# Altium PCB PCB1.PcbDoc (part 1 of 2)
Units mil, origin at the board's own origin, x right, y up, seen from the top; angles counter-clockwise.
Board outline 1968.5 x 1968.5 mil, 2 copper layers (Top Layer, Bottom Layer); 81 components, 57 nets, 327 pads, 270 vias.
Unrouted connection lines stored in the file: 104.
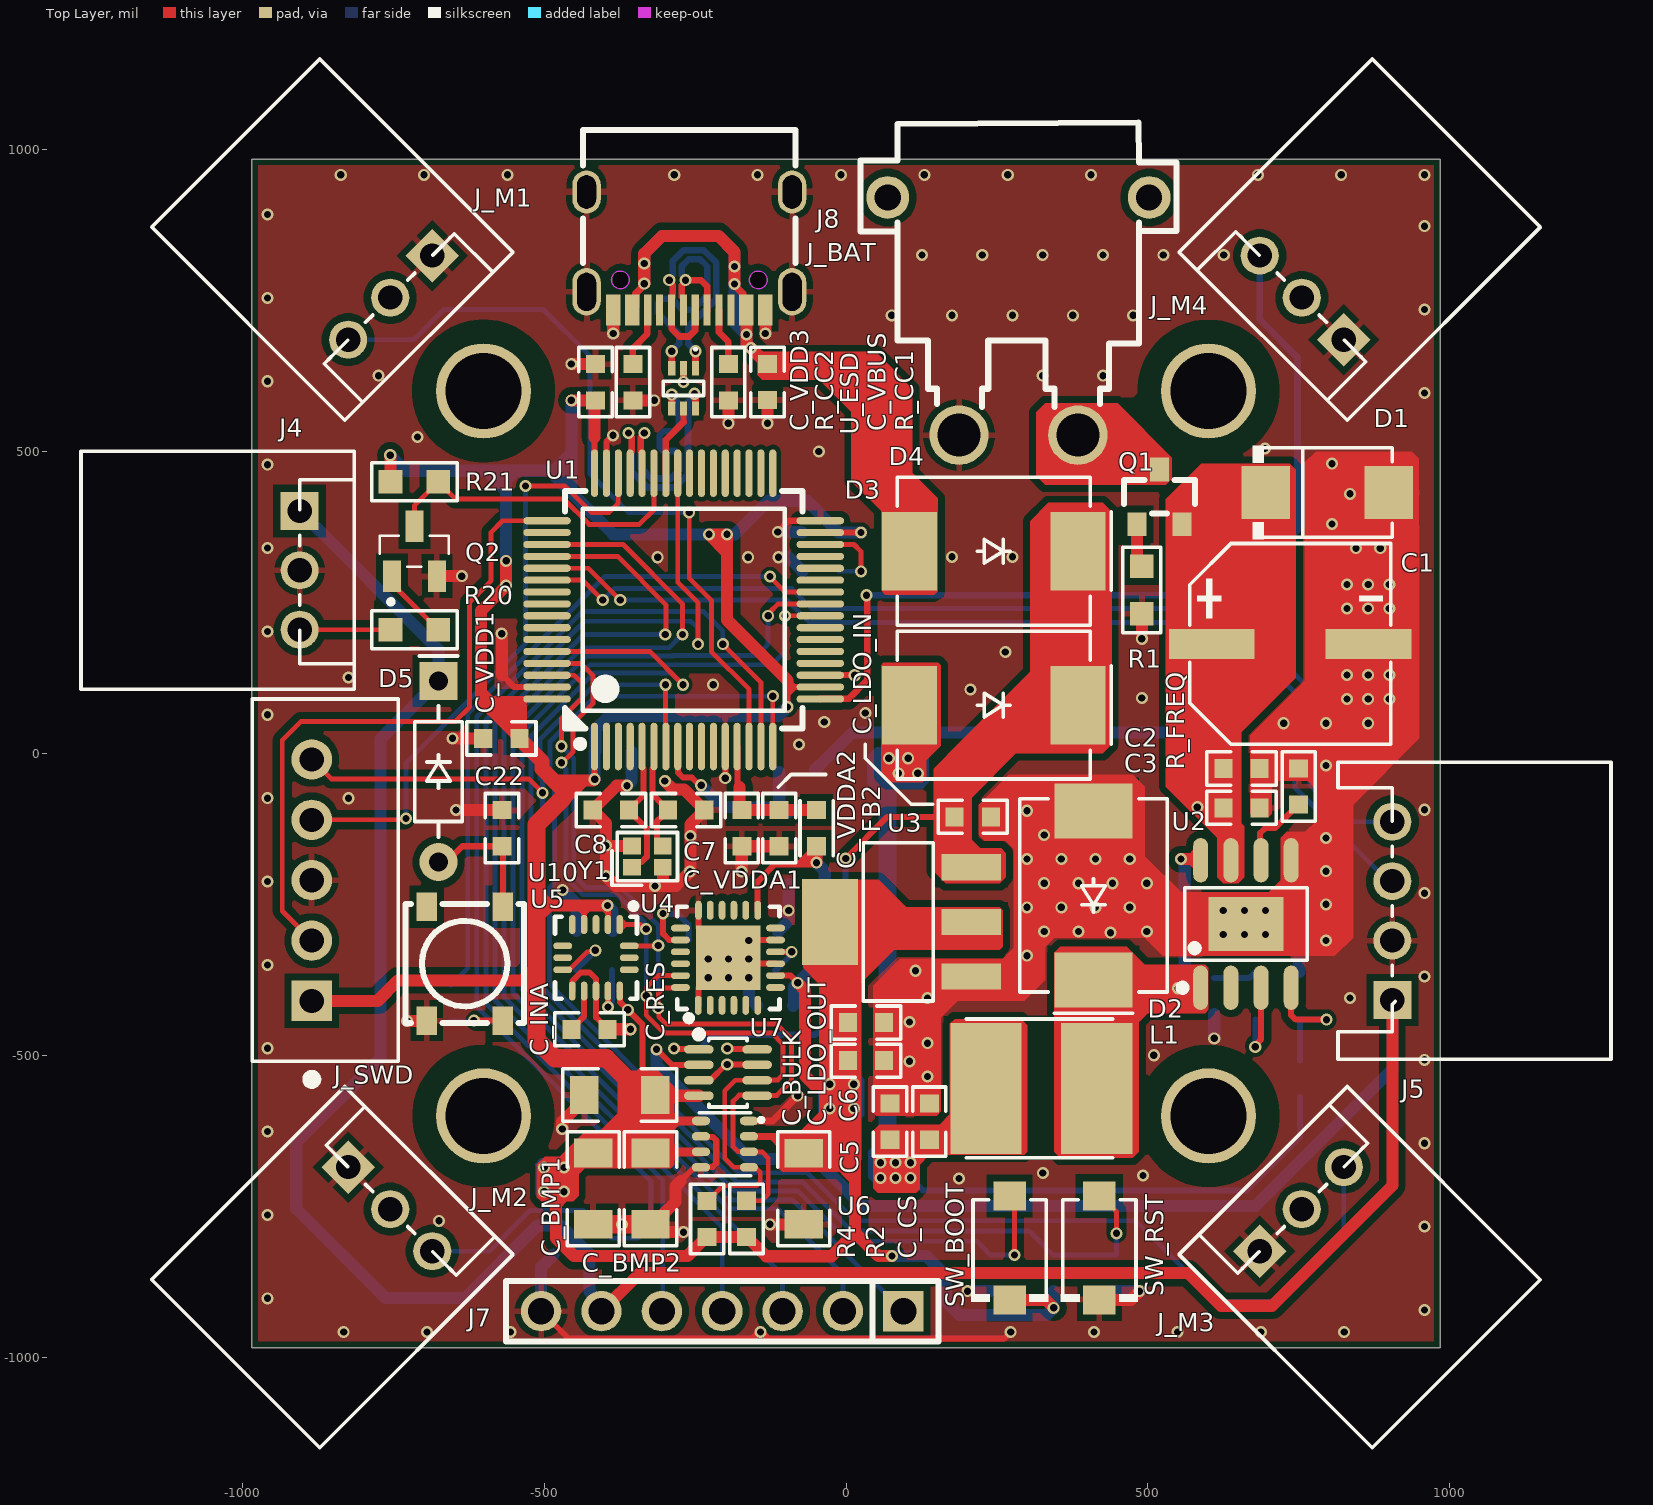
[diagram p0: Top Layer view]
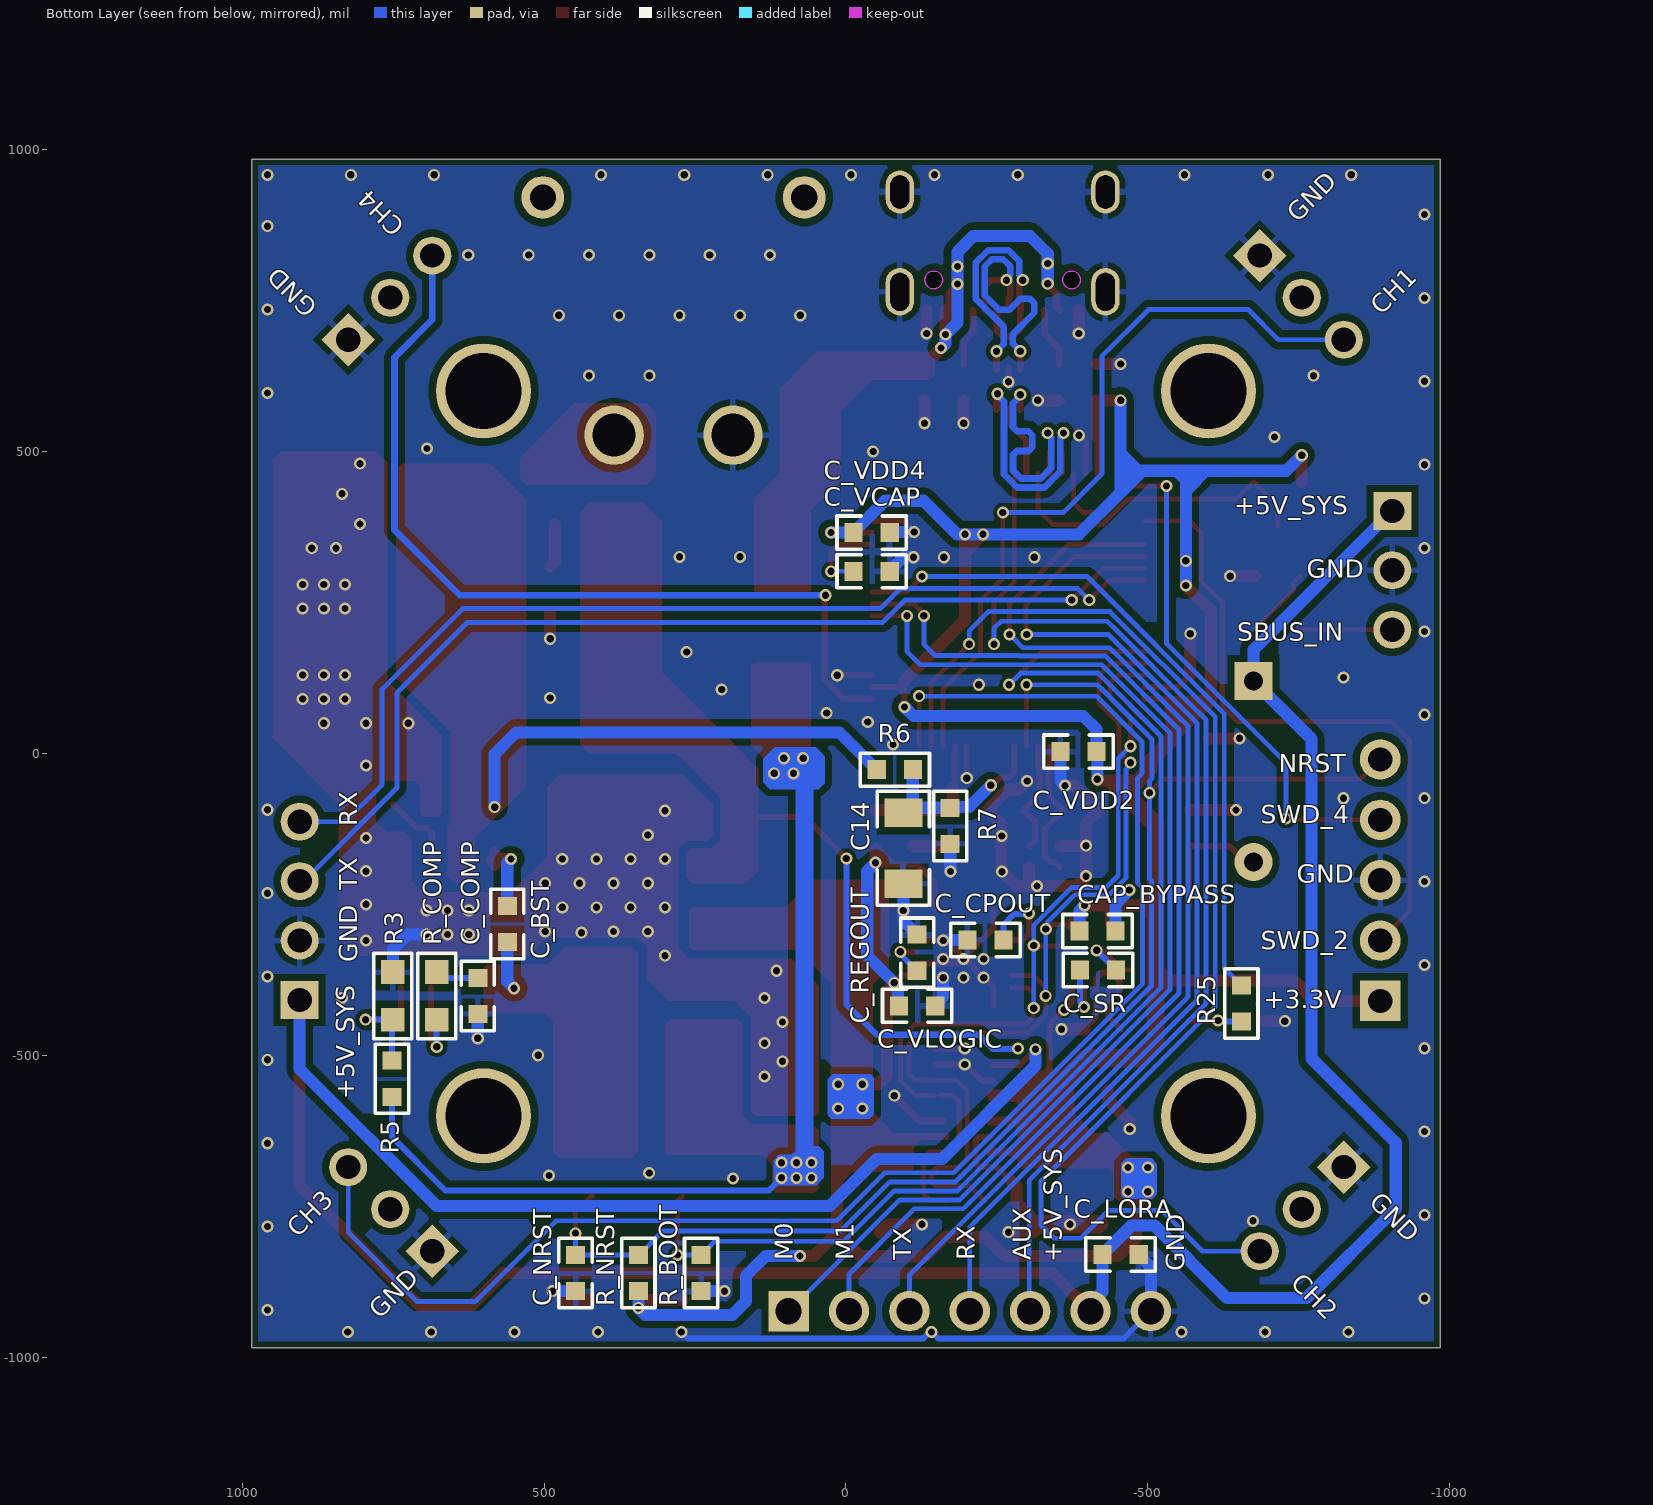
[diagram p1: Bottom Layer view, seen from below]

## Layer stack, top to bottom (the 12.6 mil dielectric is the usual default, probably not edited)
Top Solder: solder mask 0.4, Solder Resist, Dk 3.5
Top Layer: signal copper 1.4
Dielectric 1: dielectric 12.6, FR-4, Dk 4.8
Bottom Layer: signal copper 1.4
Bottom Solder: solder mask 0.4, Solder Resist, Dk 3.5

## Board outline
-984.25,-984.25 -984.25,984.25 984.25,984.25 984.25,-984.25

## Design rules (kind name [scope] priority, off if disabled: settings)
BoardOutlineClearance [All] p1: gap=10 ignorepadtopadclearanceinfootprint=FALSE except(0: Arc-SplitContinuation Track-SplitContinuation SMDPad-SplitContinuation THPad-SplitContinuation Via-SplitContinuation Fill-SplitContinuation Poly-SplitContinuation Region-SplitContinuation Text-SplitContinuation)
Clearance USB [WithinRoom('RoomDefinition')] p1: gap=5 ignorepadtopadclearanceinfootprint=FALSE except(4: Arc-Arc Arc-Track Track-Track; 8: SMDPad-Fill SMDPad-Poly SMDPad-Region; 12: Arc-Fill Arc-Poly Arc-Region Track-Fill Track-Poly Track-Region THPad-Fill THPad-Poly THPad-Region Fill-Fill Fill-Poly Fill-Region Poly-Poly Poly-Region Region-Region)
Clearance [All] p2: gap=4 ignorepadtopadclearanceinfootprint=FALSE except(12: Arc-Fill Arc-Poly Arc-Region Track-Fill Track-Poly Track-Region SMDPad-Fill SMDPad-Poly SMDPad-Region THPad-Fill THPad-Poly THPad-Region Fill-Fill Fill-Poly Fill-Region Poly-Poly Poly-Region Region-Region)
DiffPairsRouting [InDifferentialPairClass('All Differential Pairs')] p1: maxlimit=4 minlimit=4 mostfreqgap=4 toplayer_minwidth=10.9 toplayer_maxwidth=10.9 toplayer_prefwidth=10.9 bottomlayer_minwidth=10.9 bottomlayer_maxwidth=10.9 bottomlayer_prefwidth=10.9 maxuncoupledlength=500
MatchedLengths [InDifferentialPairClass('All Differential Pairs')] p1: tolerance=5 checknetsindiffpair=TRUE checkdiffpairvsdiffpair=FALSE checkxsignals=FALSE checkothers=FALSE
PlaneClearance [All] p1: clearance=8
PlaneConnect [All] p1: planeconnectstyle=Direct reliefexpansion=20 reliefentries=4 reliefconductorwidth=10 reliefairgap=10
PolygonConnect [All] p1: thpad.connectstyle=Relief thpad.reliefconductorwidth=10 thpad.reliefentries=4 thpad.polygonreliefangle="90 Angle" thpad.airgapwidth=10 smdpad.connectstyle=Relief smdpad.reliefconductorwidth=10 smdpad.reliefentries=4 smdpad.polygonreliefangle="90 Angle" smdpad.airgapwidth=10 via.connectstyle=Direct via.reliefconductorwidth=10 via.reliefentries=4 via.polygonreliefangle="90 Angle" via.airgapwidth=10
RoomDefinition [False vs False] p1: confinementstyle=ConfineIn formatcopy=TRUE lockcomponents=FALSE outline -460,1049 -96.52,1049 -96.52,418.56 -460,418.56
RoutingVias [All] p1: holewidth=12 width=20 viastyle="Through Hole" minholewidth=12 minwidth=20 maxholewidth=12 maxwidth=20
SolderMaskExpansion [All] p1: expansion=4 istentingtop=FALSE
UnRoutedNet [All] p1: checkbadconnections=TRUE
Width PWR [InNetClass('PWR')] p1: maxlimit=100 minlimit=10 preferedwidth=20
Width [All] p2: maxlimit=100 minlimit=6 preferedwidth=8
26 further rules are at their usual default settings.

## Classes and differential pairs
component class "Room Definition1": R_CC1
net class PWR: +3.3V +5V_SYS GND NetC1_1 NetC5_1 VBUS
component class "USB-C (Power + DFU), Diode-OR, 3.3V LDO": C_BULK C_LDO_IN C_LDO_OUT C_VBUS C_VDD1 C_VDD2 C_VDD3 C_VDD4 D3 D4 J8 R_CC1 R_CC2 SW_BOOT SW_RST U3 U_ESD
component class "STM32F446RET6 Core": U1
component class "RC INPUT, STATUS LED, SWD HEADER": C22 D5 J_SWD Q2 R20 R21 R25 U10
component class "MCU Support Circuit": C7 C8 C_NRST C_VCAP C_VDDA1 C_VDDA2 FB2 R_BOOT R_NRST Y1
component class "I2C SENSORS B - BAROMETER, CURRENT MONITOR, BATTERY SENSE": C14 C_BMP1 C_BMP2 C_CS C_INA R6 R7 U6 U7
component class "I2C Sensors A- IMU and Magnetometer": C_CPOUT C_REGOUT C_RES C_SR C_VLOGIC CAP_BYPASS R2 R4 U4 U5
component class "EXTERNAL CONNECTORS": C_LORA J4 J5 J7 J_BAT J_M1 J_M2 J_M3 J_M4
component class "Battery Input, Protection, 5.2V Buck": C1 C2 C3 C5 C6 C_BST C_COMP D1 D2 L1 Q1 R1 R3 R5 R_COMP R_FREQ U2
differential pair USB1: +NetJ8_A6 -NetJ8_A7
differential pair USB: +USB_DM -NetU1_45

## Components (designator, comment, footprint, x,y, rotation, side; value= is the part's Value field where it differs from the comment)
C1 "220uF" CAP-SMD_BD8.0-L8.3-W8.3-LS9.1-FD 735,180 r0 top
C2 "100nF" 0603C 654.92,-25 r0 top
C3 "10uF" 0603C 654.92,-90 r0 top
C5 "22uF" 0603C 138,-610.08 r90 top
C6 "100nF" 0603C 73,-610.08 r90 top
C7 "100nF" 0603C -264.72,-93.91 r0 top
C8 "100nF" 0603C -389.56,-93.91 r180 top
C14 "100nF" 1206C -95,-156.97 r270 bottom
C22 "100nF" 0603C -570,-123.83 r90 top
C_BMP1 "100nF" 1206C -418.69,-720.96 r270 top
C_BMP2 "100nF" 1206C -323.69,-720.96 r270 top
C_BST "100nF" 0603C 561.13,-282.56 r270 bottom
C_BULK "2.2uF" 0603C 33.35,-445.98 r0 top
C_COMP "150pF" 0603C 610,-401.63 r270 bottom
C_CPOUT "100nF" 0603C -230.92,-309 r180 bottom
C_CS "100nF" 1206C -70,-721 r270 top
C_INA "100nF" 1206C -374.87,-566 r180 top
C_LDO_IN "10uF" 0603C 210,-105 r0 top
C_LDO_OUT "22uF" 0603C 33.35,-508.98 r0 top
C_LORA "100nF" 0603C -455,-830 r180 bottom
C_NRST "100nF" 0603C 448,-860.92 r270 bottom
C_REGOUT "100nF" 0603C -118,-330.08 r90 bottom
C_RES "100nF" 0603C -425,-456.94 r0 top
C_SR "100nF" 0603C -417.45,-358.84 r180 bottom
C_VBUS "10uF" 0603C -130,615.08 r270 top
C_VCAP "100nF" 0603C -42.53,301.73 r180 bottom
C_VDD1 "100nF" 0603C -571,25 r180 top
C_VDD2 "100nF" 0603C -385,3 r0 bottom
C_VDD3 "100nF" 0603C -415,614.92 r90 top
C_VDD4 "100nF" 0603C -42.53,365.78 r180 bottom
C_VDDA1 "100nF" 0603C -172.64,-123.83 r270 top
C_VDDA2 "100nF" 0603C -110.64,-123.83 r270 top
C_VLOGIC "100nF" 0603C -117.92,-418 r180 bottom
CAP_BYPASS "100nF" 0603C -416.53,-294.38 r180 bottom
D1 "SMBJ15A" SMB_L4.6-W3.5-LS5.3-RD 800,435 r0 top
D2 "SS34-E3/9AT" SMC-2_7R94X5R91-H2R34_C 410,-235.24 r90 top
D3 "SS34-E3/9AT" SMC-2_7R94X5R91-H2R34_C 244.76,80 r180 top
D4 "SS34-E3/9AT" SMC-2_7R94X5R91-H2R34_C 244.76,335 r180 top
D5 "1N4148" DO35-2_D2R00X4R20-H2R00-P7R62 -675,-30 r270 top
FB2 "BLM18AG121SN1D" 0603L -48.64,-123.83 r90 top
J4 "S3B-XH-A(LF)(SN)" CONN-TH_S3B-XH-A-LF-SN -905,303.42 r90 top
J5 "S4B-XH-A(LF)(SN)" CONN-TH_S4B-XH-A-LF-SN 905,-260.79 r270 top
J7 "TSW-107-05-G-S" HDR-TH_7P-P2.54-V-M -205,-924 r180 top
J8 "TYPE-C-31-M-12" USB-C_SMD-TYPE-C-31-M-12 -259.57,832.24 r180 top
J_BAT "XT30APW-M" CONN-TH_XT30APW-M 285,845 r180 top
J_M1 "S3B-XH-A(LF)(SN)" CONN-TH_S3B-XH-A-LF-SN -755,755 r45 top
J_M2 "S3B-XH-A(LF)(SN)" CONN-TH_S3B-XH-A-LF-SN -755,-755 r135 top
J_M3 "S3B-XH-A(LF)(SN)" CONN-TH_S3B-XH-A-LF-SN 755,-755 r225 top
J_M4 "S3B-XH-A(LF)(SN)" CONN-TH_S3B-XH-A-LF-SN 755,755 r315 top
J_SWD "2.54-1*5" ZX-XH2_54-5PZZ -885,-210 r90 top
L1 "CY54-15UH" IND-SMD_L5.8-W5.2 323,-550 r0 top
Q1 "DMP3098L-7" SOT-23_L2.9-W1.3-P1.90-LS2.4-BR 520,430 r270 top
Q2 "MMBT3904" SOT23-3-1R90-2R90X1R30-H1R12 -715,335 r90 top
R1 "100kΩ" 0805R 490,270.63 r270 top
R2 "2.2kΩ" 0603R -165,-770.92 r90 top
R3 "10kΩ" 0805R 751,-401.63 r90 bottom
R4 "2kΩ" 0603R -230,-771 r90 top
R5 "55kΩ" 0603R 752,-538.92 r90 bottom
R6 "3kΩ" 0603R -80.83,-27 r180 bottom
R7 "10kΩ" 0603R -172.64,-119.96 r270 bottom
R20 "10kΩ" 0805R -715,205 r180 top
R21 "10kΩ" 0805R -715,450 r0 top
R25 "100Ω" 0603R -655,-414.08 r90 bottom
R_BOOT "10kΩ" 0603R 240,-860.92 r270 bottom
R_CC1 "5.1kΩ" 0603R -195,614.92 r270 top
R_CC2 "5.1kΩ" 0603R -353,614.92 r270 top
R_COMP "100kΩ" 0805R 678,-401.63 r90 bottom
R_FREQ "200kΩ" 0603R 750,-55 r90 top
R_NRST "10kΩ" 0603R 344,-860.92 r90 bottom
SW_BOOT "TS-1088-AR02016" SW-SMD_L3.9-W3.0-P4.45 272.32,-814 r270 top
SW_RST "TS-1088-AR02016" SW-SMD_L3.9-W3.0-P4.45 421,-814 r270 top
U1 "STM32F446RET6" LQFP-64_L10.0-W10.0-P0.50-LS12.0-BL -269.64,237.09 r0 top
U2 "MP1584EN-LF-Z-JSM" ESOP-8_L4.9-W3.9-P1.27-LS6.0-BL-EP-2 662.56,-282.56 r0 top
U3 "AMS1117-3.3" SOT-223-3_L6.5-W3.4-P2.30-LS7.0-BR 92.36,-275.17 r0 top
U4 "MPU-6050" QFN-24_L4.0-W4.0-P0.50-BL-EP2.7 -195,-338.52 r0 top
U5 "QMC5883L" LGA-16_L3.0-W3.0-P0.50-TL -415,-337.98 r270 top
U6 "BMP280" SENSOR-TH_BMP280-BL -200.36,-644.4 r0 top
U7 "INA219AIDCNT" SOT-23-8_L2.9-W1.6-P0.65-LS2.8-BR -194.96,-524.4 r180 top
U10 "WS2812B-V7" LED-SMD_5050WS2812B -630,-345 r270 top
U_ESD "USBLC6-2P6" SOT563-6_1R60X1R20-H0R55-P0R50 -269,604.7 r180 top
Y1 "24MHz" CRYSTAL-SMD_4P-L2.0-W1.6-BL-1 -327.68,-173.37 r0 top

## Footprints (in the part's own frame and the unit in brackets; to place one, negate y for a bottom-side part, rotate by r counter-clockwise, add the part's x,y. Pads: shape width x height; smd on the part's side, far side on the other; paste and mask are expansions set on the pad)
0603C [mm]
  rect 0.76x0.8 smd: 1(-0.76,0) 2(0.76,0)
  silkscreen extent -1.46,-0.7 1.46,0.7
0603L [mm]
  rect 0.76x0.8 smd: 1(-0.76,0) 2(0.76,0)
  silkscreen extent -1.15,-0.7 1.15,0.7
0603R [mm]
  rect 0.76x0.8 smd: 1(-0.76,0) 2(0.76,0)
  silkscreen extent -1.46,-0.7 1.46,0.7
0805R [mm]
  rect 1x1 smd: 1(-1,0) 2(1,0)
  silkscreen extent -1.8,-0.8 1.8,0.8
1206C [mm]
  rect 1.2x1.6 smd: 1(-1.5,0) 2(1.5,0)
  silkscreen extent -2.4,-1.1 2.4,1.1
CAP-SMD_BD8.0-L8.3-W8.3-LS9.1-FD [mil]
  rect 142.1x49.6 smd paste+0 mask+2: 1(-128.95,1.4) 2(130.45,1.4)
  silkscreen extent -166,-165 167,168
CONN-TH_S3B-XH-A-LF-SN [mm]
  rect 1.6x1.6 hole 1.016 paste-2539.97 mask+0.076: 1(2.5,0)
  round 1.6 hole 1.016 paste-2539.97 mask+0.076: 2(0,0) 3(-2.5,0)
  silkscreen extent -5,-2.3 5,9.2, body extent -5.18,-2.48 5.18,9.38, height 0.25
CONN-TH_S4B-XH-A-LF-SN [mm]
  rect 1.6x1.6 hole 1.016 paste-2539.97 mask+0.076: 1(3.75,0)
  round 1.6 hole 1.016 paste-2539.97 mask+0.076: 2(1.25,0) 3(-1.25,0) 4(-3.75,0)
  silkscreen extent -6.25,-2.3 6.25,9.2, body extent -6.43,-2.48 6.43,9.38, height 0.25
CONN-TH_XT30APW-M [mm]
  round 2.5 hole 1.8 paste-2539.97 mask+0.051: 1(-2.517,8.07) 2(2.483,8.07)
  round 1.8 hole 1.1 paste-2539.97 mask+0.051: 3(5.483,-1.93) 4(-5.517,-1.93)
  silkscreen extent -6.67,-5.08 6.63,6.88
CRYSTAL-SMD_4P-L2.0-W1.6-BL-1 [mil]
  rect 29.5x27.6 smd paste+0 mask+2: 1(-27,-15.3) 2(24.2,-15.3) 3(24.2,20.1) 4(-27,20.1)
  silkscreen extent -60,-45 49,42
DO35-2_D2R00X4R20-H2R00-P7R62 [mil]
  rect 63x63 / inner round 63 / far side rect 63x63 hole 32 paste-99999 mask+2.95: 1(-150,0)
  round 63 hole 32 paste-99999 mask+2.95: 2(150,0)
  silkscreen extent -191,-39 109,39, body extent -84,-40 84,40, height 10
ESOP-8_L4.9-W3.9-P1.27-LS6.0-BL-EP-2 [mm]
  oval 0.63x1.865 smd paste+0 mask+0.051: 1(-1.905,-2.682) 2(-0.635,-2.682) 3(0.635,-2.682) 4(1.905,-2.682) 5(1.905,2.682) 6(0.635,2.682) 7(-0.635,2.682) 8(-1.905,2.682)
  rect 3.15x2.26 smd paste+0 mask+0.05: 9(0,0)
  silkscreen extent -2.82,-2.83 2.58,1.52
HDR-TH_7P-P2.54-V-M [mm]
  rect 1.7x1.7 hole 1.1: 1(-7.62,0)
  round 1.7 hole 1.1: 2(-5.08,0) 3(-2.54,0) 4(0,0) 5(2.54,0) 6(5.08,0) 7(7.62,0)
  silkscreen extent -9.1,-1.27 9.1,1.27
IND-SMD_L5.8-W5.2 [mm]
  rect 3x5.5 smd paste-100 mask+0.05: 1(2.34,-0.127) 2(-2.31,-0.127)
  silkscreen extent -3.13,-3.05 3.02,2.79
LED-SMD_5050WS2812B [mm]
  rect 1.2x0.85 smd paste+0 mask+0.051: 1(-2.321,1.56) 2(-2.321,-1.64) 3(2.479,-1.64) 4(2.479,1.56)
  silkscreen extent -2.42,-2.54 2.58,2.46
LGA-16_L3.0-W3.0-P0.50-TL [mil]
  oval 31.5x11 smd paste+0 mask+2: 1(-54.56,40.25) 2(-54.56,20.55) 3(-54.56,0.85) 4(-54.56,-18.85) 5(-54.56,-38.55) 9(55.64,-38.55) 10(55.64,-18.85) 11(55.64,0.85) 12(55.64,20.55) 13(55.64,40.25)
  oval 11x31.5 smd paste+0 mask+2: 6(-19.16,-54.25) 7(0.54,-54.25) 8(20.24,-54.25) 14(20.24,55.95) 15(0.54,55.95) 16(-19.16,55.95)
  silkscreen extent -90,-67 68,69
LQFP-64_L10.0-W10.0-P0.50-LS12.0-BL [mm]
  oval 0.3x2 smd paste+0 mask+0.051: 1(-3.731,-5.731) 2(-3.231,-5.731) 3(-2.731,-5.731) 4(-2.231,-5.731) 5(-1.731,-5.731) 6(-1.231,-5.731) 7(-0.731,-5.731) 8(-0.231,-5.731) 9(0.269,-5.731) 10(0.769,-5.731) 11(1.269,-5.731) 12(1.769,-5.731) 13(2.269,-5.731) 14(2.769,-5.731) 15(3.269,-5.731) 16(3.769,-5.731) 33(3.769,5.769) 34(3.269,5.769) 35(2.769,5.769) 36(2.269,5.769) 37(1.769,5.769) 38(1.269,5.769) 39(0.769,5.769) 40(0.269,5.769) 41(-0.231,5.769) 42(-0.731,5.769) 43(-1.231,5.769) 44(-1.731,5.769) 45(-2.231,5.769) 46(-2.731,5.769) 47(-3.231,5.769) 48(-3.731,5.769)
  oval 2x0.3 smd paste+0 mask+0.051: 17(5.769,-3.731) 18(5.769,-3.231) 19(5.769,-2.731) 20(5.769,-2.231) 21(5.769,-1.731) 22(5.769,-1.231) 23(5.769,-0.731) 24(5.769,-0.231) 25(5.769,0.269) 26(5.769,0.769) 27(5.769,1.269) 28(5.769,1.769) 29(5.769,2.269) 30(5.769,2.769) 31(5.769,3.269) 32(5.769,3.769) 49(-5.731,3.769) 50(-5.731,3.269) 51(-5.731,2.769) 52(-5.731,2.269) 53(-5.731,1.769) 54(-5.731,1.269) 55(-5.731,0.769) 56(-5.731,0.269) 57(-5.731,-0.231) 58(-5.731,-0.731) 59(-5.731,-1.231) 60(-5.731,-1.731) 61(-5.731,-2.231) 62(-5.731,-2.731) 63(-5.731,-3.231) 64(-5.731,-3.731)
  silkscreen extent -4.98,-5.77 5.02,5.02
QFN-24_L4.0-W4.0-P0.50-BL-EP2.7 [mm]
  oval 0.28x0.8 smd paste-100 mask+0.05: 1(-1.262,-2) 2(-0.763,-2) 3(-0.262,-2) 4(0.237,-2) 5(0.738,-2) 6(1.237,-2) 13(1.237,2) 14(0.738,2) 15(0.237,2) 16(-0.262,2) 17(-0.763,2) 18(-1.255,2)
  oval 0.8x0.28 smd paste-100 mask+0.05: 7(1.988,-1.25) 8(1.988,-0.75) 9(1.988,-0.25) 10(1.988,0.25) 11(1.988,0.75) 12(1.988,1.25) 19(-2.012,1.25) 20(-2.012,0.75) 21(-2.012,0.25) 22(-2.012,-0.25) 23(-2.012,-0.75) 24(-2.012,-1.25)
  rect 2.7x2.7 smd paste-100 mask+0.05: 25(0,0)
  silkscreen extent -2.15,-2.79 2.15,2.15
SENSOR-TH_BMP280-BL [mil]
  oval 30.2x14.3 smd paste+0 mask+2: 1(39.5,35.6) 2(39.5,10) 3(39.5,-15.6) 4(39.5,-41.2) 5(-39.9,-41.2) 6(-39.9,-15.6) 7(-39.9,10) 8(-39.9,35.6)
  silkscreen extent -43,-55 63,49
SMB_L4.6-W3.5-LS5.3-RD [mil]
  rect 80.61x88.23 smd paste+0 mask+2: 1(-104.69,-2.74) 2(99.34,-2.74)
  silkscreen extent -126,-80 105,75
SMC-2_7R94X5R91-H2R34_C [mil]
  rect 90.98x130 smd mask+1.97: 1(-139.76,0) 2(139.76,0)
  silkscreen extent -195,-122 160,122, body extent -157,-117 157,117, height 10
SOT23-3-1R90-2R90X1R30-H1R12 [mm]
  rect 1.321x0.762 smd paste+0 mask+0.076: 1(-1.05,0.95) 2(-1.05,-0.95) 3(1.05,0)
  silkscreen extent -2.23,-1.45 0.65,1.45, body extent -0.67,-1.47 0.67,1.47, height 0.25
SOT563-6_1R60X1R20-H0R55-P0R50 [mm]
  rect 0.305x0.61 smd mask+0.05: 1(-0.5,-0.85)
  rect 0.305x0.6 smd mask+0.05: 2(0,-0.85) 3(0.5,-0.85) 4(0.5,0.85) 5(0,0.85) 6(-0.5,0.85)
  silkscreen extent -0.85,-1.7 0.85,0.3, body extent -0.82,-0.63 0.82,0.63, height 0.25
SOT-23-8_L2.9-W1.6-P0.65-LS2.8-BR [mm]
  oval 1.252x0.35 smd paste+0 mask+0.051: 1(1.24,-0.867) 2(1.24,-0.217) 3(1.24,0.433) 4(1.239,1.084) 5(-1.213,1.084) 6(-1.213,0.433) 7(-1.213,-0.217) 8(-1.213,-0.867)
  silkscreen extent -0.8,-1.65 1.39,1.56
SOT-23_L2.9-W1.3-P1.90-LS2.4-BR [mm]
  rect 1x0.8 smd paste+0 mask+0.051: 1(1.276,-0.964) 2(1.276,0.936) 3(-1.024,-0.014)
  silkscreen extent -0.57,-1.51 0.83,1.49
SOT-223-3_L6.5-W3.4-P2.30-LS7.0-BR [mm]
  rect 2.5x1.1 smd paste+0 mask+0.051: 1(2.919,-2.403) 2(2.919,-0.103) 3(2.919,2.197)
  rect 2.34x3.6 smd paste+0 mask+0.051: 4(-3.021,-0.103)
  silkscreen extent -1.62,-3.43 1.32,3.22
SW-SMD_L3.9-W3.0-P4.45 [mm]
  rect 1.23x1.36 smd paste+0 mask+0.051: 1(-2.052,-0.034) 2(2.318,-0.034)
  silkscreen extent -1.89,-1.65 2.39,1.58
USB-C_SMD-TYPE-C-31-M-12 [mm]
  oval 1.2x2 hole 0.8 slot 1.6 at 90 deg paste-2539.97 mask+0.051: 1(-4.325,1.716) 4(4.325,1.716)
  oval 1.2x1.8 hole 0.8 slot 1.4 at 90 deg paste-2539.97 mask+0.051: 2(-4.325,-2.484) 3(4.325,-2.484)
  rect 0.6x1.3 smd paste-100 mask+0.051: A1B12(-3.2,2.484) A4B9(-2.4,2.484) B1A12(3.2,2.484) B4A9(2.4,2.484)
  rect 0.3x1.3 smd paste-100 mask+0.051: A5(-1.25,2.484) A6(-0.25,2.484) A7(0.25,2.484) A8(1.25,2.484) B5(1.75,2.484) B6(0.75,2.484) B7(-0.75,2.484) B8(-1.75,2.484)
  Keep-Out Layer board cut-out: 3.275,1.216 3.239,1.053 3.134,0.922 2.984,0.849 2.816,0.849 2.666,0.922 2.561,1.053 2.524,1.216 2.525,1.216 2.561,1.379 2.666,1.51 2.816,1.582 2.984,1.582 3.134,1.51 3.239,1.379 3.276,1.216
  Keep-Out Layer board cut-out: -2.525,1.216 -2.561,1.053 -2.666,0.922 -2.816,0.849 -2.984,0.849 -3.134,0.922 -3.239,1.053 -3.276,1.216 -3.275,1.216 -3.239,1.379 -3.134,1.51 -2.984,1.582 -2.816,1.582 -2.666,1.51 -2.561,1.379 -2.524,1.216
  Keep-Out Layer circle w0.003: c2.9,1.216 r0.375
  Keep-Out Layer circle w0.003: c-2.9,1.216 r0.375
  Keep-Out Layer region: 3.275,1.216 3.239,1.053 3.134,0.922 2.984,0.849 2.816,0.849 2.666,0.922 2.561,1.053 2.524,1.216 2.525,1.216 2.561,1.379 2.666,1.51 2.816,1.582 2.984,1.582 3.134,1.51 3.239,1.379 3.276,1.216
  Keep-Out Layer region: -2.525,1.216 -2.561,1.053 -2.666,0.922 -2.816,0.849 -2.984,0.849 -3.134,0.922 -3.239,1.053 -3.276,1.216 -3.275,1.216 -3.239,1.379 -3.134,1.51 -2.984,1.582 -2.816,1.582 -2.666,1.51 -2.561,1.379 -2.524,1.216
  Keep-Out Layer region: 3.275,1.216 3.266,1.132 3.238,1.053 3.193,0.982 3.134,0.922 3.063,0.878 2.983,0.85 2.9,0.841 2.816,0.85 2.737,0.878 2.666,0.922 2.607,0.982 2.562,1.053 2.534,1.132 2.525,1.216 2.534,1.299 2.562,1.378 2.607,1.449 2.666,1.509 2.737,1.554 2.816,1.581 2.9,1.591 2.983,1.581 3.063,1.554 3.134,1.509 3.193,1.449 3.238,1.378 3.266,1.299 3.275,1.216
  Keep-Out Layer region: -2.525,1.216 -2.534,1.132 -2.562,1.053 -2.607,0.982 -2.666,0.922 -2.737,0.878 -2.816,0.85 -2.9,0.841 -2.983,0.85 -3.063,0.878 -3.134,0.922 -3.193,0.982 -3.238,1.053 -3.266,1.132 -3.275,1.216 -3.266,1.299 -3.238,1.378 -3.193,1.449 -3.134,1.509 -3.063,1.554 -2.983,1.581 -2.9,1.591 -2.816,1.581 -2.737,1.554 -2.666,1.509 -2.607,1.449 -2.562,1.378 -2.534,1.299 -2.525,1.216
  silkscreen extent -4.47,-5.08 4.47,0.5
ZX-XH2_54-5PZZ [mil]
  rect 67x67 / inner round 67 / far side rect 67x67 hole 40 paste-99999 mask+2.95: 1(-200,0)
  round 67 hole 40 paste-99999 mask+2.95: 2(-100,0) 3(0,0) 4(100,0) 5(200,0)
  silkscreen extent -338,-144 300,99, body extent -295,-139 295,94

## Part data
C1: library part "RVT1V221M0810 220UF 35V", "Capacitance:220uF Tolerance:±20% Tolerance:±20% Voltage Rating:35V Ripple Current:195mA@120Hz Equivalent Series Resistance(ESR):- Diameter:8mm Height - Seated (Max):10.2mm Lifetime:2800hrs@105℃ Operating Temperature:-55℃~+105℃ Operating Temperature:-55℃~+", Equivalent Series Resistance(ESR)=-, JLCPCB Part Class="Extended Part", LCSC Part Name="220uF ±20% 35V", Manufacturer=DMBJ(振宝佳), Operating Temperature=-55℃~+105℃, Ripple Current=195mA@120Hz, Tolerance=±20%, Voltage Rating=35V
C2 C6 C22 C_BST C_REGOUT C_RES C_SR C_VDD1 C_VDD2 C_VDD3 C_VDD4 C_VLOGIC CAP_BYPASS: library part CT41G-0603-2X1-50V-0.1uF-K(N), "Capacitance:100nF Tolerance:±10% Tolerance:±10% Voltage Rating:50V Temperature Coefficient:-", JLCPCB Part Class="Extended Part", LCSC Part Name="100nF ±10% 50V", Manufacturer=TORCH(火炬), Temperature Coefficient=-, Tolerance=±10%, Voltage Rating=50V
C3 C_LDO_IN C_VBUS: library part 0603X106M250NT, "Capacitance:10uF Tolerance:±20% Tolerance:±20% Voltage Rating:25V Temperature Coefficient:X5R", JLCPCB Part Class="Extended Part", LCSC Part Name="10uF ±20% 25V", Manufacturer=FH(风华), Temperature Coefficient=X5R, Tolerance=±20%, Voltage Rating=25V
C5: library part CC0603MRX6S5BB226, "Capacitance:22uF Tolerance:±20% Tolerance:±20% Voltage Rating:6.3V Temperature Coefficient:X6S", JLCPCB Part Class="Extended Part", LCSC Part Name="22uF ±20% 6.3V", Manufacturer=YAGEO(国巨), Temperature Coefficient=X6S, Tolerance=±20%, Voltage Rating=6.3V
C7 C8 C_NRST C_VCAP C_VDDA1 C_VDDA2: library part CC0603KRX7R9BB104, "Capacitance:100nF Tolerance:±10% Tolerance:±10% Voltage Rating:50V Temperature Coefficient:X7R", JLCPCB Part Class="Basic Part", LCSC Part Name="100nF ±10% 50V", Manufacturer=YAGEO(国巨), Temperature Coefficient=X7R, Tolerance=±10%, Voltage Rating=50V
C14 C_BMP1 C_BMP2 C_CS C_INA: library part CGA1206M3L104J101MT, "Capacitance:100nF Tolerance:±5% Tolerance:±5% Voltage Rating:100V Temperature Coefficient:-", JLCPCB Part Class="Extended Part", LCSC Part Name="100nF ±5% 100V", Manufacturer=HRE(芯声), Temperature Coefficient=-, Tolerance=±5%, Voltage Rating=100V
C_BULK: library part 0603X225M160NT, "Capacitance:2.2uF Tolerance:±20% Tolerance:±20% Voltage Rating:16V", JLCPCB Part Class="Extended Part", LCSC Part Name="2.2uF ±20% 16V", Manufacturer=FH(风华), Tolerance=±20%, Voltage Rating=16V
C_COMP: library part CC0603CG50V151JN, "Capacitance:150pF Tolerance:±5% Tolerance:±5% Voltage Rating:50V Temperature Coefficient:", JLCPCB Part Class="Extended Part", LCSC Part Name="150pF ±5% 50V", Manufacturer=TORCH(火炬), Tolerance=±5%, Voltage Rating=50V
C_CPOUT: library part 0603B104K500CT, "Capacitance: Tolerance:±10% Tolerance:±10% Voltage Rated: Temperature Coefficient:", JLCPCB Part Class="Extended Part", LCSC Part Name="100nF ±10% 50V", Manufacturer=Walsin(华新科), Tolerance=±10%
C_LDO_OUT: library part FCC0603X226M160CT, "Capacitance:22uF Tolerance:±20% Tolerance:±20% Voltage Rating:16V Temperature Coefficient:X5R Operating Temperature:-55℃~+85℃ Operating Temperature:-55℃~+85℃", JLCPCB Part Class="Extended Part", LCSC Part Name="22uF ±20% 16V", Manufacturer=FOJAN(富捷), Operating Temperature=-55℃~+85℃, Temperature Coefficient=X5R, Tolerance=±20%, Voltage Rating=16V
C_LORA: library part 06035C104K4T2A, "Capacitance:100nF Tolerance:±10% Tolerance:±10% Voltage Rating:50V Temperature Coefficient:X7R", JLCPCB Part Class="Extended Part", LCSC Part Name="100nF ±10% 50V", Manufacturer="Kyocera AVX", Temperature Coefficient=X7R, Tolerance=±10%, Voltage Rating=50V
D1: library part SMBJ15A_C2912077, "Polarity:Unidirectional Reverse Stand-Off Voltage (Vrwm):15V Clamping Voltage:24.4V Peak Pulse Current (Ipp):24.6A Peak Pulse Power Dissipation (Ppp):600W Voltage - Breakdown:18.5V Reverse Leakage Current (Ir):1uA Number of Channels:1 Operating Temperatur", Clamping Voltage=24.4V, JLCPCB Part Class="Extended Part", LCSC Part Name="单向TVS 15V截止 峰值浪涌电流：24.6A", Manufacturer=LRC(乐山无线电), Operating Temperature=-55℃~+150℃, Peak Pulse Current (Ipp)=24.6A, Peak Pulse Power Dissipation (Ppp)=600W, Reverse Leakage Current (Ir)=1uA, Reverse Stand-Off Voltage (Vrwm)=15V, Voltage - Breakdown=18.5V
D2 D3 D4: "Diode Configuration:1 Independent Voltage - Forward(Vf@If):500mV@3A Voltage - DC Reverse(Vr):40V Current - Rectified:3A Reverse Leakage Current (Ir):500uA@40V Operating Junction Temperature Range:-55℃~+150℃ Operating Junction Temperature Range:-55℃~+150℃", Current - Rectified=3A, JLCPCB Part Class="Extended Part", LCSC Part Name="电压:40V 电流:3A", Manufacturer=VISHAY(威世), Non-Repetitive Peak Forward Surge Current=100A, Operating Junction Temperature Range=-55℃~+150℃, Reverse Leakage Current (Ir)=500uA@40V, Voltage - DC Reverse(Vr)=40V, Voltage - Forward(Vf@If)=500mV@3A
D5: library part 1N4148_C18195411, "Diode Configuration:1 Independent Pd - Power Dissipation:500mW Current - Rectified:150mA Voltage - DC Reverse(Vr):100V Voltage - Forward(Vf@If):1V@10mA Non-Repetitive Peak Forward Surge Current:500mA Reverse Leakage Current (Ir):5mA Reverse Recovery Time", Current - Rectified=150mA, JLCPCB Part Class="Extended Part", LCSC Part Name="100V 150mA", Manufacturer=LJ(朗捷), Non-Repetitive Peak Forward Surge Current=500mA, Operating Junction Temperature Range=-60℃~+200℃, Pd - Power Dissipation=500mW, Reverse Leakage Current (Ir)=5mA, Voltage - DC Reverse(Vr)=100V, Voltage - Forward(Vf@If)=1V@10mA
FB2: "Impedance @ Frequency:120Ω@100MHz Tolerance:±25% Tolerance:±25% DC Resistance(DCR):180mΩ Current Rating:800mA Number of Circuits:1 Operating Temperature:-55℃~+125℃ Operating Temperature:-55℃~+125℃", Current Rating=800mA, DC Resistance(DCR)=180mΩ, Impedance @ Frequency=120Ω@100MHz, JLCPCB Part Class="Extended Part", LCSC Part Name="单路 0603磁珠 阻抗120Ω@100MHz", Manufacturer=muRata(村田), Operating Temperature=-55℃~+125℃, Tolerance=±25%
J4 J_M1 J_M2 J_M3 J_M4: "Pins Structure:1x3P Pitch:2.5mm Mounting Style:Bend insert Reference Series:XH Number of Pins:3P Number of Rows:1 Number of PINs Per Row:3 Row Spacing:- Current Rating (Max):3A Contact Material:Brass Contact Plating:Tin Operating Temperature Range:-25℃~+8", Colour=White, Current Rating (Max)=3A, Flame Retardant Rating=UL94V-0, JLCPCB Part Class="Extended Part", LCSC Part Name="1x3P 间距:2.5mm 弯插 系列:XH", Manufacturer=JST, Operating Temperature Range=-25℃~+85℃, Rated Voltage (Max)=250V
J5: "Pins Structure:1x4P Pitch:2.5mm Mounting Type:Right Angle Reference Series:XH Number of Pins:4P Number of Rows:1 Number of PINs Per Row:4 Row Spacing:- Current Rating:3A Contact Material:Brass Contact Plating:Tin Operating Temperature:-25℃~+85℃ Operating", Color=White, Current Rating=3A, Flame Retardant Rating=UL94V-0, JLCPCB Part Class="Extended Part", LCSC Part Name="1x4P 间距:2.5mm 弯插 系列:XH", Manufacturer=JST, Operating Temperature=-25℃~+85℃, Voltage Rating=250V
J7: "Pitch:2.54mm Mounting Type:Through Hole Number of Rows:1 Number of Pins:7P Contact Material:Phosphor Bronze Contact Plating:Gold Operating Temperature:-55℃~+125℃ Operating Temperature:-55℃~+125℃ Color:Black", Color=Black, JLCPCB Part Class="Extended Part", LCSC Part Name="间距:2.54mm 直插", Manufacturer=SAMTEC, Operating Temperature=-55℃~+125℃
J8: "Connector Type:Type-C Protocol Standard:- Gender:Female Mounting Type:Surface Mount, Right Angle Number of Contacts:16P Number of Ports:1 Current Rating-Power:5A Voltage Rating:20V Connect-Disconnect Life:10,000 cycles Length:7.35mm Operating Temperature:", Current Rating-Power=5A, JLCPCB Part Class="Extended Part", LCSC Part Name="Type-C 母 卧贴", Manufacturer=韩国韩荣, Operating Temperature=-30℃~+80℃, Voltage Rating=20V
J_BAT: JLCPCB Part Class="Extended Part", LCSC Part Name="AMASS(艾迈斯)防水锁扣镀金15A二芯插头 PCB板卧式 黄色 公头XT30APW-M", Manufacturer=AMASS(艾迈斯)
J_SWD: "Pin Structure:1x5P Pitch:2.54mm Circluar Pins/Square Pins:Pin Header Mounting Type:Through Hole Number of Rows:1 Number of Pins:5P Current Rating:2.5A Length of Mating Pin:6mm Insulation Height:2.54mm Length of End Connection Pin:3mm Contact Material:Bras", Current Rating=2.5A, JLCPCB Part Class="Extended Part", LCSC Part Name="1x5P 间距:2.54mm 方针 直插", Manufacturer=ZHOURI(洲日), Operating Temperature=-40℃~+105℃
L1: JLCPCB Part Class="Extended Part", LCSC Part Name="15uH ±10%", Manufacturer="SHOU HAN(首韩)"
Q1: "Number:1 P-Channel Drain to Source Voltage:30V Current - Continuous Drain(Id):3.8A RDS(on):120mΩ@4.5V Pd - Power Dissipation:1.08W Gate Threshold Voltage (Vgs(th)):2.1V Gate Charge(Qg):8nC@4.5V Input Capacitance(Ciss):336pF Reverse Transfer Capacitance (C", Current - Continuous Drain(Id)=3.8A, Drain to Source Voltage=30V, Gate Threshold Voltage (Vgs(th))=2.1V, Input Capacitance(Ciss)=336pF, JLCPCB Part Class="Extended Part", LCSC Part Name="1个P沟道 耐压:30V 电流:3.8A", Manufacturer=DIODES(美台), Operating Temperature=-55℃~+150℃, Output Capacitance(Coss)=210pF, Pd - Power Dissipation=1.08W, Reverse Transfer Capacitance (Crss@Vds)=147pF
Q2: library part MMBT3904_C51953474, "type:NPN Current - Collector(Ic):200mA Collector - Emitter Voltage VCEO:40V Pd - Power Dissipation:200mW DC Current Gain:300 DC Current Gain:300 Transition frequency(fT):300MHz Current - Collector Cutoff:100nA Vce Saturation(VCE(sat)):300mV Operating Temp", Collector - Emitter Voltage VCEO=40V, Current - Collector Cutoff=100nA, Current - Collector(Ic)=200mA, DC Current Gain=300, Emitter-Base Voltage(Vebo)=6V, JLCPCB Part Class="Extended Part", LCSC Part Name="MMBT3904 hFE:100-300 NPN 晶体管 电流：200mA 电压：40V", Manufacturer=CCX(晁禾), Operating Temperature=-55℃~+150℃, Pd - Power Dissipation=200mW, Transition frequency(fT)=300MHz
R1 R_COMP: library part CR0805J80104G, "Type:Thick Film Resistors Resistance: Tolerance:±5% Tolerance:±5% Power(Watts): Overload Voltage (Max): Temperature Coefficient:±200ppm/℃ Temperature Coefficient:±200ppm/℃ Operating Temperature Range:-55℃~+125℃ Operating Temperature Range:-55℃~+125℃", JLCPCB Part Class="Extended Part", LCSC Part Name="厚膜电阻 100kΩ ±5% 125mW", Manufacturer=LIZ(丽智电子), Operating Temperature Range=-55℃~+125℃, Temperature Coefficient=±200ppm/℃, Tolerance=±5%
R2: library part RMC06032.2K5%N, "Type:Thick Film Resistor Resistance:2.2kΩ Tolerance:±5% Tolerance:±5% Power(Watts):100mW Voltage-Supply(Max):50V Temperature Coefficient:±100ppm/℃ Temperature Coefficient:±100ppm/℃ Operating Temperature:-55℃~+155℃ Operating Temperature:-55℃~+155℃", JLCPCB Part Class="Extended Part", LCSC Part Name="厚膜电阻 2.2kΩ ±5% 100mW", Manufacturer=Tyohm(幸亚电阻), Operating Temperature=-55℃~+155℃, Power(Watts)=100mW, Temperature Coefficient=±100ppm/℃, Tolerance=±5%, Voltage-Supply(Max)=50V
R3 R20 R21: library part 0805W8F1002T5E, "Type:Thick Film Resistor Resistance:10kΩ Tolerance:±1% Tolerance:±1% Power(Watts):125mW Voltage-Supply(Max):150V Temperature Coefficient:±100ppm/℃ Temperature Coefficient:±100ppm/℃ Operating Temperature:-55℃~+155℃ Operating Temperature:-55℃~+155℃", JLCPCB Part Class="Basic Part", LCSC Part Name="厚膜电阻 10kΩ ±1%", Manufacturer=UNI-ROYAL(厚声), Operating Temperature=-55℃~+155℃, Power(Watts)=125mW, Temperature Coefficient=±100ppm/℃, Tolerance=±1%, Voltage-Supply(Max)=150V
R4: library part 0603WAF2001T5E, "Type:Thick Film Resistor Resistance:2kΩ Tolerance:±1% Tolerance:±1% Power(Watts):100mW Voltage-Supply(Max):75V Temperature Coefficient:±100ppm/℃ Temperature Coefficient:±100ppm/℃ Operating Temperature:-55℃~+155℃ Operating Temperature:-55℃~+155℃", JLCPCB Part Class="Basic Part", LCSC Part Name="厚膜电阻 2kΩ ±1%", Manufacturer=UNI-ROYAL(厚声), Operating Temperature=-55℃~+155℃, Power(Watts)=100mW, Temperature Coefficient=±100ppm/℃, Tolerance=±1%, Voltage-Supply(Max)=75V
R5: library part CR165502F, "Type:Thick Film Resistor Resistance:55kΩ Tolerance:±1% Tolerance:±1% Power(Watts):100mW Temperature Coefficient:±100ppm/℃ Temperature Coefficient:±100ppm/℃ Operating Temperature:-55℃~+155℃ Operating Temperature:-55℃~+155℃", JLCPCB Part Class="Extended Part", LCSC Part Name="厚膜电阻 55kΩ ±1% 100mW", Manufacturer=Meritek, Operating Temperature=-55℃~+155℃, Power(Watts)=100mW, Temperature Coefficient=±100ppm/℃, Tolerance=±1%
R6: library part RMC06033K5%N, "Type:Thick Film Resistor Resistance:3kΩ Tolerance:±5% Tolerance:±5% Power(Watts):100mW Voltage-Supply(Max):50V Temperature Coefficient:±100ppm/℃ Temperature Coefficient:±100ppm/℃ Operating Temperature:-55℃~+155℃ Operating Temperature:-55℃~+155℃", JLCPCB Part Class="Extended Part", LCSC Part Name="厚膜电阻 3kΩ ±5% 100mW", Manufacturer=Tyohm(幸亚电阻), Operating Temperature=-55℃~+155℃, Power(Watts)=100mW, Temperature Coefficient=±100ppm/℃, Tolerance=±5%, Voltage-Supply(Max)=50V
R7: library part PTFR0603Q10K0N9, "Type:Thin Film Resistor Resistance:10kΩ Tolerance:±0.02% Tolerance:±0.02% Power(Watts):100mW Voltage-Supply(Max):100V Temperature Coefficient:±10ppm/℃ Temperature Coefficient:±10ppm/℃ Operating Temperature:-55℃~+155℃ Operating Temperature:-55℃~+155℃", JLCPCB Part Class="Extended Part", LCSC Part Name="薄膜电阻 10kΩ ±0.02% 100mW", Manufacturer=RESI(开步睿思), Operating Temperature=-55℃~+155℃, Power(Watts)=100mW, Temperature Coefficient=±10ppm/℃, Tolerance=±0.02%, Voltage-Supply(Max)=100V
R25: library part TD03G1000FT, "Type:Thin Film Resistor Resistance:100Ω Tolerance:±1% Tolerance:±1% Power(Watts):100mW Voltage-Supply(Max):50V Temperature Coefficient:±25ppm/℃ Temperature Coefficient:±25ppm/℃ Operating Temperature:-55℃~+155℃ Operating Temperature:-55℃~+155℃", JLCPCB Part Class="Extended Part", LCSC Part Name="薄膜电阻 100Ω ±1% 100mW", Manufacturer=FH(风华), Operating Temperature=-55℃~+155℃, Power(Watts)=100mW, Temperature Coefficient=±25ppm/℃, Tolerance=±1%, Voltage-Supply(Max)=50V
R_BOOT R_NRST: library part RC0603JR-0710KL, "Type:Thick Film Resistor Resistance:10kΩ Tolerance:±5% Tolerance:±5% Power(Watts):100mW Voltage-Supply(Max):75V Temperature Coefficient:±100ppm/℃ Temperature Coefficient:±100ppm/℃ Operating Temperature:-55℃~+155℃ Operating Temperature:-55℃~+155℃", JLCPCB Part Class="Extended Part", LCSC Part Name="厚膜电阻 10kΩ ±5% 100mW", Manufacturer=YAGEO(国巨), Operating Temperature=-55℃~+155℃, Power(Watts)=100mW, Temperature Coefficient=±100ppm/℃, Tolerance=±5%, Voltage-Supply(Max)=75V
R_CC1 R_CC2: library part "FRC0603J512 TS", "Type:Thick Film Resistor Resistance:5.1kΩ Tolerance:±5% Tolerance:±5% Power(Watts):100mW Voltage-Supply(Max):75V Temperature Coefficient:±100ppm/℃ Temperature Coefficient:±100ppm/℃ Operating Temperature:-55℃~+155℃ Operating Temperature:-55℃~+155℃", JLCPCB Part Class="Extended Part", LCSC Part Name="5.1kΩ ±5% 100mW 厚膜电阻", Manufacturer=FOJAN(富捷), Operating Temperature=-55℃~+155℃, Power(Watts)=100mW, Temperature Coefficient=±100ppm/℃, Tolerance=±5%, Voltage-Supply(Max)=75V
R_FREQ: library part FRC0603F2003TS, "Type:Thick Film Resistor Resistance:200kΩ Tolerance:±1% Tolerance:±1% Power(Watts):100mW Voltage-Supply(Max):75V Temperature Coefficient:±100ppm/℃ Temperature Coefficient:±100ppm/℃ Operating Temperature:-55℃~+155℃ Operating Temperature:-55℃~+155℃", JLCPCB Part Class="Extended Part", LCSC Part Name="200kΩ ±1% 100mW 厚膜电阻", Manufacturer=FOJAN(富捷), Operating Temperature=-55℃~+155℃, Power(Watts)=100mW, Temperature Coefficient=±100ppm/℃, Tolerance=±1%, Voltage-Supply(Max)=75V
SW_BOOT SW_RST: "Circuit:SPST Actuator Style:Round Button Operating Force:1.6N Mounting Type:Surface Mount,Vertical Length:3.9mm Width:3mm Switch Height:2mm with Bracket:Without Bracket Contact Current:50mA Voltage Rating:12V Actuator/Cap Color:Black With Lamp:- IP Rating", Actuator/Cap Color=Black, Contact Current=50mA, IP Rating=-, JLCPCB Part Class="Basic Part", LCSC Part Name="3.9*3*2mm 立贴 轻触开关", Manufacturer=XUNPU(讯普), Operating Force=1.6N, Operating Temperature=-30℃~+80℃, Voltage Rating=12V
U1: "CPU Core:ARM Cortex-M4 CPU Maximum Speed:180MHz Core Size:32 Bit Program Storage Size:512KB Program Memory Type:FLASH RAM Size:128KB EEPROM:- Number of I/O:50 ADC (Bit):12bit DAC (Bit):12bit Oscillator Type:Built-in Voltage - Supply:1.7V~3.6V Voltage - Su", JLCPCB Part Class="Extended Part", LCSC Part Name="MSL{}3 带DSP和FPU的高性能基础系列ARM Cortex-M4 MCU，具有512 KB Flash、180 MHz CPU、ART加速器和双QSPI", Manufacturer=ST(意法半导体), Operating Temperature=-40℃~+85℃, Voltage - Supply=1.7V~3.6V
U2: "Function:Step-down type Voltage - Supply:4.5V~40V Voltage - Supply:4.5V~40V Output Voltage:800mV~37V Output Voltage:800mV~37V Output Current:3A Frequency - Switching:100kHz~220kHz Frequency - Switching:100kHz~220kHz Operating Temperature:-40℃~+125℃ Operat", Frequency - Switching=100kHz~220kHz, JLCPCB Part Class="Extended Part", LCSC Part Name=异步降压转换器，采用电流模式控制，具备多种保护功能, Manufacturer=JSMSEMI(杰盛微), Operating Temperature=-40℃~+125℃, Output Current=3A, Output Voltage=800mV~37V, Quiescent Current=65uA, Voltage - Supply=4.5V~40V
U3: library part AMS1117-3.3_C18212698, "Output Configuration:Positive Voltage - Supply:12V Output Voltage:3.3V Output Voltage:3.3V Output Current:1A Power Supply Rejection Ratio (PSRR):- Voltage Dropout:1.3V@(1A) standby current:4mA Noise:- Features:Over Current Protection；Thermal shutdown Oper", JLCPCB Part Class="Extended Part", LCSC Part Name="3.3V 1A 12V", Manufacturer="TECH PUBLIC(台舟)", Operating Temperature=-50℃~+140℃, Output Current=1A, Output Voltage=3.3V, Power Supply Rejection Ratio (PSRR)=-, standby current=4mA, Voltage - Supply=12V, Voltage Dropout=1.3V@(1A)
U4: "Accelerometer Sensing Axis:X,Y,Z Acceleration Measurement Range (MAX):±16g Acceleration Measurement Range (MAX):±16g Gyroscope Sensing Axis:X,Y,Z Gyroscope Measurement Range (MAX):±2000dps Gyroscope Measurement Range (MAX):±2000dps Sensor Type:IMU (accele", JLCPCB Part Class="Extended Part", Manufacturer="TDK InvenSense(应美盛)", Operating Temperature=-40℃~+85℃, standby current=5uA, Voltage - Supply=2.375V~3.46V
U5: "Magnetic Sensing Range(X,Y):±8Gs Magnetic Sensing Range(X,Y):±8Gs Magnetic Sensing Range(Z):±8Gs Magnetic Sensing Range(Z):±8Gs Output bit:16bit Interface Type:I2C Voltage - Supply:2.16V~3.6V Voltage - Supply:2.16V~3.6V Current - Supply:75uA Operating Tem", Current - Supply=75uA, JLCPCB Part Class="Extended Part", LCSC Part Name="三轴磁传感器 停产", Manufacturer=QST(上海矽睿), Operating Temperature=-40℃~+85℃, Voltage - Supply=2.16V~3.6V
U6: "Pressure range:30Kpa~1.1bar Pressure range:30Kpa~1.1bar Voltage - Supply:1.71V~3.6V Voltage - Supply:1.71V~3.6V Standby Current:300nA Interface:SPI；I2C Module:- Absolute Accuracy:1hpa Relative Accuracy:0.12hpa Features:Standby mode；Integrated ADC and digi", JLCPCB Part Class="Extended Part", LCSC Part Name="BMP280 停产", Manufacturer=Bosch(博世), Operating Temperature=-40℃~+85℃, standby current=300nA, Temperature Coefficient of Offset(TCO)=1.5pa/K, Voltage - Supply=1.71V~3.6V
U7: "Number of Channels:- Vcm - Common Mode Voltage:0V~26V Vcm - Common Mode Voltage:0V~26V Gain:- Bandwidth:- Ib - Input Bias Current:20nA Vos - Input Offset Voltage:10uV Operating Temperature:-40℃~+125℃ Operating Temperature:-40℃~+125℃ Differential Voltage:±", Differential Voltage=±26V, Ib - Input Bias Current=20nA, Input Offset Voltage Drift(Vos TC)=0.1uV/℃, JLCPCB Part Class="Extended Part", LCSC Part Name=具有I2C接口的零漂移双向电流/功率监测计, Manufacturer=TI(德州仪器), Operating Temperature=-40℃~+125℃, Output Current=-, Quiescent Current=700uA, Vcm - Common Mode Voltage=0V~26V, Vos - Input Offset Voltage=10uV
U10: JLCPCB Part Class="Extended Part", Manufacturer=worldsemi
U_ESD: library part USBLC6-2P6_C49451919, "Polarity:Unidirectional Reverse Stand-Off Voltage (Vrwm):5V Clamping Voltage:14V Peak Pulse Current (Ipp):5.5A Peak Pulse Power Dissipation (Ppp):80W Voltage - Breakdown:6V Reverse Leakage Current (Ir):80nA Number of Channels:2 Operating Temperature:-55℃~", Clamping Voltage=14V, JLCPCB Part Class="Extended Part", Junction Capacitance=0.5pF, LCSC Part Name="单向 5V 5.5A", Manufacturer=R+O(宏嘉诚), Operating Temperature=-55℃~+150℃, Peak Pulse Current (Ipp)=5.5A, Peak Pulse Power Dissipation (Ppp)=80W, Reverse Leakage Current (Ir)=80nA, Reverse Stand-Off Voltage (Vrwm)=5V, Voltage - Breakdown=6V
Y1: library part XRCGB24M000F3M00R0, "Type:Crystal Oscillator Frequency:24MHz Normal temperature Frequency Tolerance:±30ppm Normal temperature Frequency Tolerance:±30ppm Load Capacitance:6pF Frequency Stability:±40ppm Frequency Stability:±40ppm Equivalent Series Resistance(ESR):150Ω Operating", Equivalent Series Resistance(ESR)=150Ω, Frequency Stability=±40ppm, JLCPCB Part Class="Extended Part", LCSC Part Name="24MHz ±30ppm 6pF", Load Capacitance=6pF, Manufacturer=muRata(村田), Normal temperature Frequency Tolerance=±30ppm, Operating Temperature=-30℃~+85℃

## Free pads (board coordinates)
  round 157.48 hole 125.98: 1(-600.39,-600.39) 1(-600.39,600.39) 1(600.39,-600.39) 1(600.39,600.39)

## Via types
v1: diameter 20, hole 12, Top Layer to Bottom Layer, tented both sides, 270 vias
